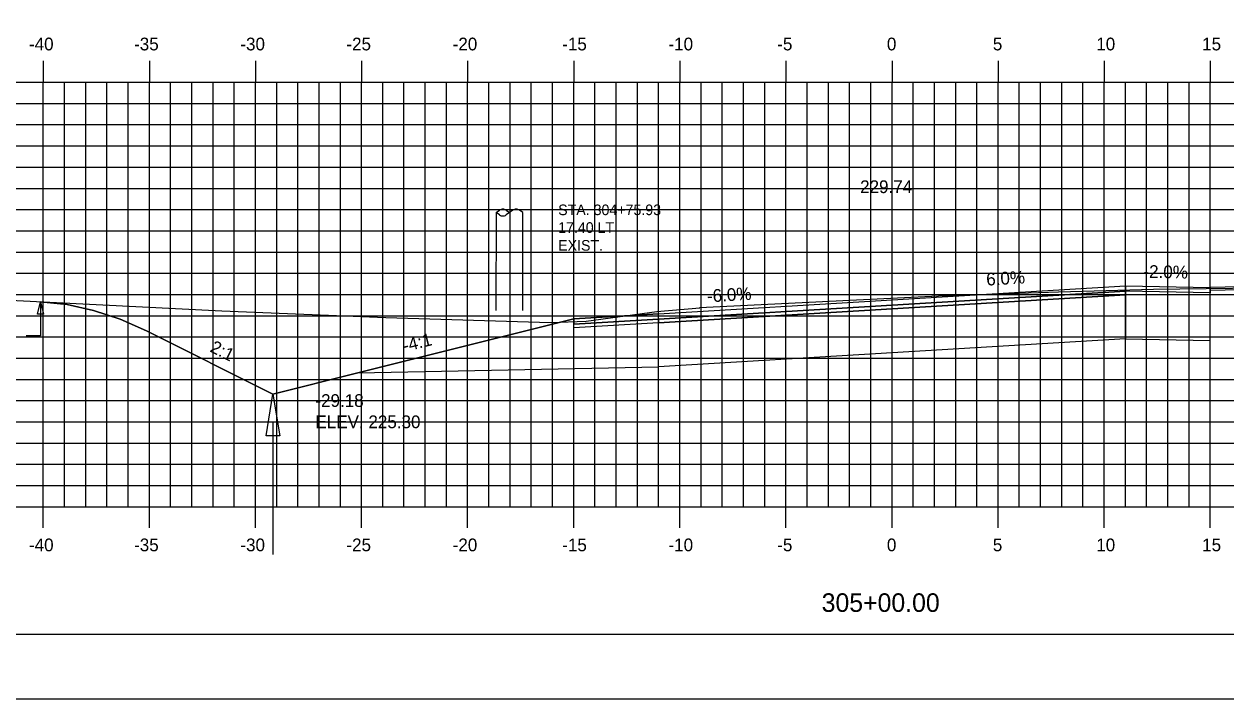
# Model space of a CAD drawing. Extents: x 1137211 to 1137381, y 608981 to 609091.
# Drawn here: x 1137253 to 1137309.6, y 608981.3 to 609013.1 of the extents above; entities that cross this region are included whole.
import ezdxf

# ---------------------------------------------------------------- set-up
doc = ezdxf.new("R2010")
doc.units = 0
for name, color, linetype in [('ANNOTATION', 7, 'Continuous'), ('BORDER', 7, 'Continuous'), ('D_Drainage_Ditch_Line', 7, 'Continuous'), ('D_Roadway_Centerline', 7, 'Continuous'), ('D_Roadway_Centerline_Text', 7, 'Continuous'), ('D_Roadway_Edge_Shoulder', 7, 'Continuous'), ('D_Roadway_Edge_TW', 7, 'Continuous'), ('D_Roadway_Pavement', 7, 'Continuous'), ('D_Roadway_SlopeLines', 7, 'Continuous'), ('D_Roadway_SubGrade', 7, 'Continuous'), ('D_Text_Monospaced', 7, 'Continuous'), ('D_Text_Standard', 7, 'Continuous'), ('H_V ANNOTATION', 7, 'Continuous'), ('MAJOR', 7, 'Continuous'), ('MINOR', 7, 'Continuous'), ('PLOT BOUNDARY', 7, 'Continuous'), ('S_Roadway_Centerline', 7, 'Continuous'), ('S_Utilities_Pole_StreetLight', 7, 'Continuous')]:
    doc.layers.add(name, color=color, linetype=linetype)

msp = doc.modelspace()

# ---------------------------------------------------------------- linework, layer by layer
msp.add_lwpolyline([(1137253.766, 608999.991), (1137255.016, 608999.857), (1137256.266, 608999.583), (1137257.516, 608999.168), (1137258.766, 608998.614), (1137264.721, 608995.636), (1137268.721, 608996.636), (1137278.895, 608999.179), (1137278.896, 608999.179), (1137282.896, 608999.419), (1137293.896, 609000.079), (1137304.896, 609000.739), (1137308.896, 609000.659)])
at = {"layer": 'BORDER'}
msp.add_lwpolyline([(1137218.897, 608984.335), (1137378.897, 608984.335), (1137378.897, 609089.335), (1137218.897, 609089.335)], close=True, dxfattribs=at)
at = {"layer": 'D_Drainage_Ditch_Line'}
msp.add_line((1137264.721, 608994.323), (1137264.721, 608988.08), dxfattribs=at)
msp.add_lwpolyline([(1137265.049, 608993.667), (1137264.393, 608993.667), (1137264.721, 608995.636)], close=True, dxfattribs=at)
at = {"layer": 'D_Roadway_Edge_Shoulder'}
for points in [[(1137355.366, 609001.58), (1137351.367, 609001.609), (1137308.896, 609000.659), (1137308.896, 609000.534), (1137351.367, 609001.484), (1137355.365, 609001.455)], [(1137304.896, 609000.739), (1137308.896, 609000.659), (1137308.896, 609000.409), (1137304.896, 609000.489)], [(1137282.896, 608999.419), (1137278.896, 608999.179), (1137278.896, 608998.929), (1137282.896, 608999.169)]]:
    msp.add_lwpolyline(points, close=True, dxfattribs=at)
at = {"layer": 'D_Roadway_Edge_TW'}
for points in [[(1137282.896, 608999.169), (1137282.896, 608999.419), (1137293.896, 609000.079), (1137304.896, 609000.739), (1137304.896, 609000.489), (1137293.896, 608999.829)], [(1137282.896, 608999.003), (1137278.896, 608998.763), (1137278.896, 608998.929), (1137282.896, 608999.169)]]:
    msp.add_lwpolyline(points, close=True, dxfattribs=at)
at = {"layer": 'D_Roadway_Pavement'}
msp.add_lwpolyline([(1137282.896, 608999.003), (1137282.896, 608999.169), (1137293.896, 608999.829), (1137304.896, 609000.489), (1137304.896, 609000.323), (1137293.896, 608999.663)], close=True, dxfattribs=at)
at = {"layer": 'D_Roadway_SlopeLines'}
for points in [[(1137264.721, 608995.636), (1137258.766, 608998.614), (1137257.516, 608999.168), (1137256.266, 608999.583), (1137255.016, 608999.857), (1137253.766, 608999.991)], [(1137268.721, 608996.636), (1137264.721, 608995.636)]]:
    msp.add_lwpolyline(points, dxfattribs=at)
at = {"layer": 'D_Roadway_SubGrade'}
for points in [[(1137308.896, 608999.659), (1137308.896, 609000.659), (1137308.896, 609000.659), (1137308.896, 609000.409), (1137304.896, 609000.489), (1137304.896, 609000.323), (1137304.896, 608998.239), (1137308.896, 608998.159)], [(1137282.896, 608996.919), (1137282.896, 608999.003), (1137293.896, 608999.663), (1137304.896, 609000.323), (1137304.896, 608998.239), (1137293.896, 608997.579)], [(1137282.896, 608999.003), (1137282.896, 608999.169), (1137278.896, 608998.929), (1137278.896, 608999.179), (1137278.895, 608999.179), (1137268.721, 608996.636), (1137282.896, 608996.919)]]:
    msp.add_lwpolyline(points, close=True, dxfattribs=at)
at = {"layer": 'D_Text_Standard'}
msp.add_lwpolyline([(1137253.766, 608999.991), (1137253.762, 608998.381), (1137253.082, 608998.381)], dxfattribs=at)
msp.add_lwpolyline([(1137253.766, 608999.991), (1137253.91, 608999.408), (1137253.619, 608999.409)], close=True, dxfattribs=at)
at = {"layer": 'MAJOR'}
for p, q in [((1137253.896, 609011.337), (1137253.896, 609010.335)), ((1137258.896, 609011.337), (1137258.896, 609010.335)), ((1137263.896, 609011.337), (1137263.896, 609010.335)), ((1137268.896, 609011.337), (1137268.896, 609010.335)), ((1137273.896, 609011.337), (1137273.896, 609010.335)), ((1137278.896, 609011.337), (1137278.896, 609010.335)), ((1137283.896, 609011.337), (1137283.896, 609010.335)), ((1137288.896, 609011.337), (1137288.896, 609010.335)), ((1137293.896, 609011.337), (1137293.896, 609010.335)), ((1137298.896, 609011.337), (1137298.896, 609010.335)), ((1137303.896, 609011.337), (1137303.896, 609010.335)), ((1137308.896, 609011.337), (1137308.896, 609010.335)), ((1137223.896, 609010.335), (1137363.896, 609010.335)), ((1137223.896, 609010.335), (1137363.896, 609010.335)), ((1137253.896, 608990.335), (1137253.896, 609010.335)), ((1137258.896, 608990.335), (1137258.896, 609010.335)), ((1137263.896, 608990.335), (1137263.896, 609010.335)), ((1137268.896, 608990.335), (1137268.896, 609010.335)), ((1137273.896, 608990.335), (1137273.896, 609010.335)), ((1137278.896, 608990.335), (1137278.896, 609010.335)), ((1137283.896, 608990.335), (1137283.896, 609010.335)), ((1137288.896, 608990.335), (1137288.896, 609010.335)), ((1137293.896, 608990.335), (1137293.896, 609010.335)), ((1137298.896, 608990.335), (1137298.896, 609010.335)), ((1137303.896, 608990.335), (1137303.896, 609010.335)), ((1137308.896, 608990.335), (1137308.896, 609010.335)), ((1137223.896, 609005.335), (1137363.896, 609005.335)), ((1137223.896, 609000.335), (1137363.896, 609000.335)), ((1137223.896, 608995.335), (1137363.896, 608995.335)), ((1137223.896, 608990.335), (1137363.896, 608990.335)), ((1137223.896, 608990.335), (1137363.896, 608990.335)), ((1137253.896, 608989.333), (1137253.896, 608990.335)), ((1137258.896, 608989.333), (1137258.896, 608990.335)), ((1137263.896, 608989.333), (1137263.896, 608990.335)), ((1137268.896, 608989.333), (1137268.896, 608990.335)), ((1137273.896, 608989.333), (1137273.896, 608990.335)), ((1137278.896, 608989.333), (1137278.896, 608990.335)), ((1137283.896, 608989.333), (1137283.896, 608990.335)), ((1137288.896, 608989.333), (1137288.896, 608990.335)), ((1137293.896, 608989.333), (1137293.896, 608990.335)), ((1137298.896, 608989.333), (1137298.896, 608990.335)), ((1137303.896, 608989.333), (1137303.896, 608990.335)), ((1137308.896, 608989.333), (1137308.896, 608990.335))]:
    msp.add_line(p, q, dxfattribs=at)
at = {"layer": 'MINOR'}
for p, q in [((1137254.896, 608990.335), (1137254.896, 609010.335)), ((1137255.896, 608990.335), (1137255.896, 609010.335)), ((1137256.896, 608990.335), (1137256.896, 609010.335)), ((1137257.896, 608990.335), (1137257.896, 609010.335)), ((1137259.896, 608990.335), (1137259.896, 609010.335)), ((1137260.896, 608990.335), (1137260.896, 609010.335)), ((1137261.896, 608990.335), (1137261.896, 609010.335)), ((1137262.896, 608990.335), (1137262.896, 609010.335)), ((1137264.896, 608990.335), (1137264.896, 609010.335)), ((1137265.896, 608990.335), (1137265.896, 609010.335)), ((1137266.896, 608990.335), (1137266.896, 609010.335)), ((1137267.896, 608990.335), (1137267.896, 609010.335)), ((1137269.896, 608990.335), (1137269.896, 609010.335)), ((1137270.896, 608990.335), (1137270.896, 609010.335)), ((1137271.896, 608990.335), (1137271.896, 609010.335)), ((1137272.896, 608990.335), (1137272.896, 609010.335)), ((1137274.896, 608990.335), (1137274.896, 609010.335)), ((1137275.896, 608990.335), (1137275.896, 609010.335)), ((1137276.896, 608990.335), (1137276.896, 609010.335)), ((1137277.896, 608990.335), (1137277.896, 609010.335)), ((1137279.896, 608990.335), (1137279.896, 609010.335)), ((1137280.896, 608990.335), (1137280.896, 609010.335)), ((1137281.896, 608990.335), (1137281.896, 609010.335)), ((1137282.896, 608990.335), (1137282.896, 609010.335)), ((1137284.896, 608990.335), (1137284.896, 609010.335)), ((1137285.896, 608990.335), (1137285.896, 609010.335)), ((1137286.896, 608990.335), (1137286.896, 609010.335)), ((1137287.896, 608990.335), (1137287.896, 609010.335)), ((1137289.896, 608990.335), (1137289.896, 609010.335)), ((1137290.896, 608990.335), (1137290.896, 609010.335)), ((1137291.896, 608990.335), (1137291.896, 609010.335)), ((1137292.896, 608990.335), (1137292.896, 609010.335)), ((1137294.896, 608990.335), (1137294.896, 609010.335)), ((1137295.896, 608990.335), (1137295.896, 609010.335)), ((1137296.896, 608990.335), (1137296.896, 609010.335)), ((1137297.896, 608990.335), (1137297.896, 609010.335)), ((1137299.896, 608990.335), (1137299.896, 609010.335)), ((1137300.896, 608990.335), (1137300.896, 609010.335)), ((1137301.896, 608990.335), (1137301.896, 609010.335)), ((1137302.896, 608990.335), (1137302.896, 609010.335)), ((1137304.896, 608990.335), (1137304.896, 609010.335)), ((1137305.896, 608990.335), (1137305.896, 609010.335)), ((1137306.896, 608990.335), (1137306.896, 609010.335)), ((1137307.896, 608990.335), (1137307.896, 609010.335)), ((1137223.896, 609009.335), (1137363.896, 609009.335)), ((1137223.896, 609008.335), (1137363.896, 609008.335)), ((1137223.896, 609007.335), (1137363.896, 609007.335)), ((1137223.896, 609006.335), (1137363.896, 609006.335)), ((1137223.896, 609004.335), (1137363.896, 609004.335)), ((1137223.896, 609003.335), (1137363.896, 609003.335)), ((1137223.896, 609002.335), (1137363.896, 609002.335)), ((1137223.896, 609001.335), (1137363.896, 609001.335)), ((1137223.896, 608999.335), (1137363.896, 608999.335)), ((1137223.896, 608998.335), (1137363.896, 608998.335)), ((1137223.896, 608997.335), (1137363.896, 608997.335)), ((1137223.896, 608996.335), (1137363.896, 608996.335)), ((1137223.896, 608994.335), (1137363.896, 608994.335)), ((1137223.896, 608993.335), (1137363.896, 608993.335)), ((1137223.896, 608992.335), (1137363.896, 608992.335)), ((1137223.896, 608991.335), (1137363.896, 608991.335))]:
    msp.add_line(p, q, dxfattribs=at)
at = {"layer": 'PLOT BOUNDARY'}
msp.add_lwpolyline([(1137210.803, 608981.276), (1137380.803, 608981.276), (1137380.803, 609091.276), (1137210.803, 609091.276)], close=True, dxfattribs=at)
at = {"layer": 'S_Roadway_Centerline'}
msp.add_lwpolyline([(1137223.896, 609000.377), (1137225.357, 609000.391), (1137229.531, 609000.434), (1137234.116, 609000.419), (1137239.036, 609000.317), (1137250.446, 609000.16), (1137262.307, 608999.556), (1137270.041, 608999.249), (1137277.797, 608999.017), (1137279.478, 608999.069), (1137282.816, 608999.526), (1137284.833, 608999.711), (1137284.843, 608999.713), (1137285.155, 608999.73), (1137296.08, 609000.277), (1137301.744, 609000.456), (1137306.22, 609000.583), (1137313.681, 609000.675)], dxfattribs=at)
at = {"layer": 'S_Utilities_Pole_StreetLight'}
for p, q in [((1137275.245, 609004.193), (1137275.401, 609004.304)), ((1137275.714, 609004.304), (1137275.87, 609004.193)), ((1137276.027, 609004.304), (1137275.87, 609004.193)), ((1137276.495, 609004.193), (1137276.339, 609004.304)), ((1137275.245, 608999.574), (1137275.248, 609004.193)), ((1137275.401, 609004.082), (1137275.245, 609004.193)), ((1137275.87, 609004.193), (1137275.714, 609004.082)), ((1137276.495, 608999.574), (1137276.498, 609004.193))]:
    msp.add_line(p, q, dxfattribs=at)
for centre, start, end in [((1137275.558, 609004.083), 90, 125.2644), ((1137275.558, 609004.083), 54.7356, 90), ((1137276.183, 609004.083), 90, 125.2644), ((1137276.183, 609004.083), 54.7356, 90), ((1137275.558, 609004.304), 234.7356, 270), ((1137275.558, 609004.304), 270, 305.2644)]:
    msp.add_arc(centre, 0.271, start, end, dxfattribs=at)

# ---------------------------------------------------------------- texts
at = {"layer": 'ANNOTATION'}
for s, rotation, p in [('-2.0%', 358.8542, (1137305.739, 609001.123)), ('6.0%', 3.4336, (1137298.354, 609000.749)), ('-6.0%', 3.4336, (1137285.193, 608999.959)), ('2:1', 333.4349, (1137261.71, 608997.659)), ('-4:1', 14.0362, (1137270.92, 608997.616))]:
    msp.add_text(s, height=0.6, rotation=rotation, dxfattribs=at).set_placement(p)
at = {"layer": 'D_Roadway_Centerline'}
for s, p in [('C', (1137293.891, 609000.079)), ('L', (1137293.896, 609000.072))]:
    msp.add_text(s, height=0.0146, dxfattribs=at).set_placement(p)
at = {"layer": 'D_Roadway_Centerline_Text'}
msp.add_text('229.74', height=0.6, dxfattribs=at).set_placement((1137292.393, 609005.111))
at = {"layer": 'D_Text_Monospaced'}
for s, height, p in [('STA. 304+75.93', 0.49998, (1137278.162, 609004.072)), ('17.40 LT.', 0.5, (1137278.162, 609003.238)), ('EXIST. ', 0.5, (1137278.162, 609002.398))]:
    msp.add_text(s, height=height, dxfattribs=at).set_placement(p)
at = {"layer": 'D_Text_Standard'}
for s, p in [('-29.18', (1137266.721, 608995.036)), ('ELEV. 225.30', (1137266.721, 608994.034))]:
    msp.add_text(s, height=0.6, dxfattribs=at).set_placement(p)
at = {"layer": 'H_V ANNOTATION'}
for s, height, p in [('-40', 0.6, (1137253.222, 609011.835)), ('-35', 0.6, (1137258.176, 609011.835)), ('-30', 0.6, (1137263.185, 609011.835)), ('-25', 0.6, (1137268.182, 609011.835)), ('-20', 0.6, (1137273.19, 609011.835)), ('-15', 0.6, (1137278.353, 609011.835)), ('-10', 0.6, (1137283.361, 609011.835)), ('-5', 0.6, (1137288.487, 609011.835)), ('0', 0.6, (1137293.655, 609011.835)), ('5', 0.6, (1137298.647, 609011.835)), ('10', 0.6, (1137303.522, 609011.835)), ('15', 0.6, (1137308.514, 609011.835)), ('-40', 0.6, (1137253.222, 608988.235)), ('-35', 0.6, (1137258.176, 608988.235)), ('-30', 0.6, (1137263.185, 608988.235)), ('-25', 0.6, (1137268.182, 608988.235)), ('-20', 0.6, (1137273.19, 608988.235)), ('-15', 0.6, (1137278.353, 608988.235)), ('-10', 0.6, (1137283.361, 608988.235)), ('-5', 0.6, (1137288.487, 608988.235)), ('0', 0.6, (1137293.655, 608988.235)), ('5', 0.6, (1137298.647, 608988.235)), ('10', 0.6, (1137303.522, 608988.235)), ('15', 0.6, (1137308.514, 608988.235)), ('305+00.00', 0.875, (1137290.58, 608985.378))]:
    msp.add_text(s, height=height, dxfattribs=at).set_placement(p)
at = {"layer": 'S_Roadway_Centerline'}
for s, p in [('C', (1137296.075, 609000.277)), ('L', (1137296.08, 609000.27))]:
    msp.add_text(s, height=0.0146, dxfattribs=at).set_placement(p)

doc.saveas('drawing.dxf')
